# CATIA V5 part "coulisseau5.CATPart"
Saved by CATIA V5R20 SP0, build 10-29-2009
Part number: coulisseau5
Bounding box of the stored display mesh (mm): x -5 to 5, y -13.903 to 14.161, z -10.828 to 11.721
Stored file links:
  C:\Users\thinkmotion1\Desktop\IAO OK\IAO_2010_1458_splanchena\Correction_Khaled\coulisseau5.CATPart
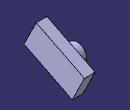
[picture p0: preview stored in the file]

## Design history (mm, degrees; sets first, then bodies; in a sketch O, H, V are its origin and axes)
Body1 (main body)
  Sketch1 on yz-plane, origin (0, 0, 0), H (0, 1, 0), V (0, 0, 1)
    line L1 (-13.9028, 0.3005) -> (-8.2257, 11.7207)
    point P1 (-13.9028, 0.3005)
    line L2 (-8.2257, 11.7207) -> (14.1608, 0.5921)
    line L3 (14.1608, 0.5921) -> (8.4837, -10.828)
    line L4 (8.4837, -10.828) -> (-13.9028, 0.3005)
    point P5 (-13.9028, 0.3005)
    length L2 = 25
    length L4 = 25
    perpendicularity: L2 L1
    parallelism: L3 L1
    coincidence: P1 P5
  Pad1: profile Sketch1, direction (1, 0, 0), length 5
  Sketch2 on end face of Pad1, origin (5, 0, 0), H (0, 1, 0), V (0, 0, 1)
    circle A1 centre (0.8822, -0.7289) radius 4.25
    radius A1 = 4.25
  Pad2: profile Sketch2, direction (-1, 0, 0), length 10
